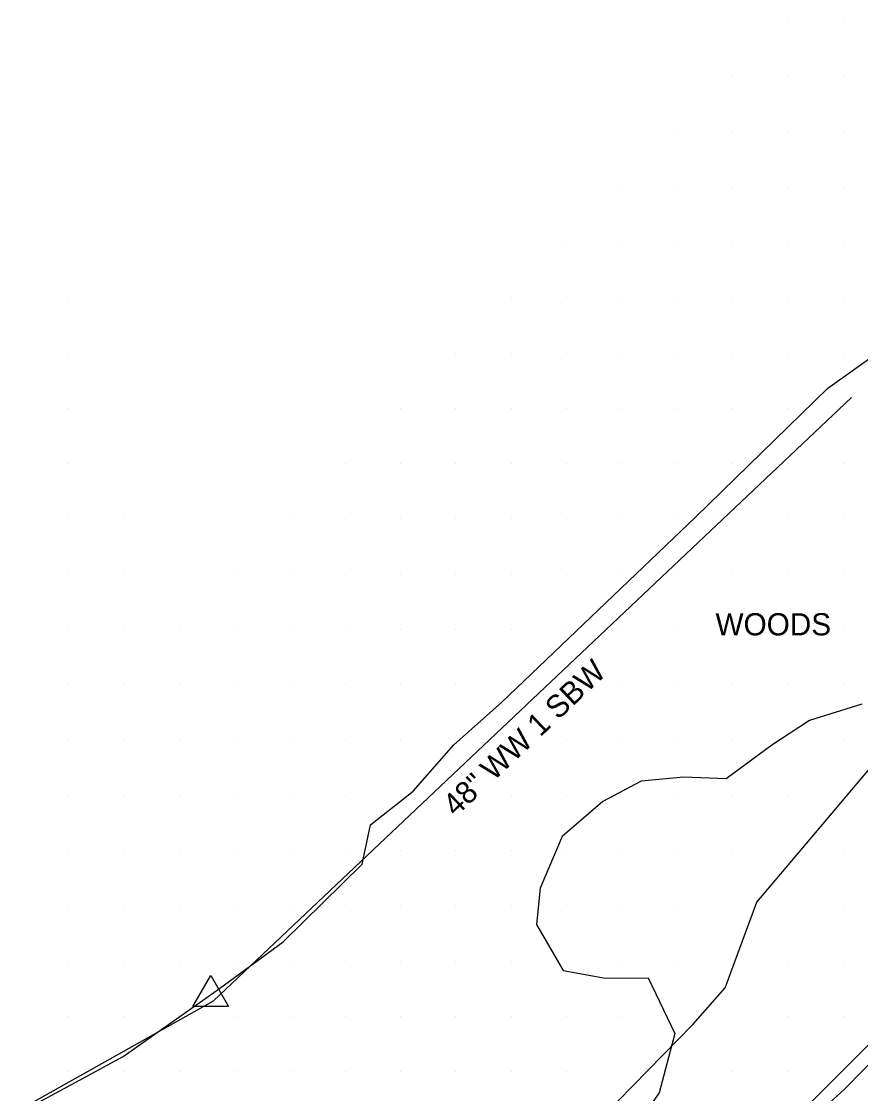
# Model space of a CAD drawing. Extents: x 1548934 to 1561348, y 809680 to 824075.
# Drawn here: x 1551931.4 to 1552083.2, y 811066.1 to 811260 of the extents above; entities that cross this region are included whole.
import ezdxf

# ---------------------------------------------------------------- set-up
doc = ezdxf.new("R2010")
doc.units = 0
for name, color, linetype in [('E_NCDOT_Vertical_Profile_Ground_Line', 7, 'Continuous'), ('Exist DTM QL2 LIDAR Elevation Point', 7, 'Continuous'), ('Exist Other Culture Fence Line Text', 7, 'Continuous'), ('Exist Vegetation Woods Line', 7, 'Continuous'), ('Exist Vegetation Woods Line Text', 7, 'Continuous'), ('P_RDY_Dimension_Text', 7, 'Continuous'), ('PH Exist DTM Breakline', 7, 'Continuous')]:
    doc.layers.add(name, color=color, linetype=linetype)

msp = doc.modelspace()

# ---------------------------------------------------------------- linework, layer by layer
at = {"layer": 'E_NCDOT_Vertical_Profile_Ground_Line'}
msp.add_line((1551965.65, 811083.67), (1551965.65, 811083.67), dxfattribs=at)
msp.add_lwpolyline([(1551962.4, 811081.78), (1551965.65, 811087.42), (1551968.9, 811081.78)], close=True, dxfattribs=at)
at = {"layer": 'Exist DTM QL2 LIDAR Elevation Point'}
for p, q in [((1552070.02, 811260.03), (1552070.02, 811260.03)), ((1552080.03, 811260.03), (1552080.03, 811260.03)), ((1552060.02, 811250.03), (1552060.02, 811250.03)), ((1552070.02, 811250.03), (1552070.02, 811250.03)), ((1552080.03, 811250.03), (1552080.03, 811250.03)), ((1552050.02, 811240.03), (1552050.02, 811240.03)), ((1552060.02, 811240.03), (1552060.02, 811240.03)), ((1552070.02, 811240.03), (1552070.02, 811240.03)), ((1552080.03, 811240.03), (1552080.03, 811240.03)), ((1552040.02, 811230.03), (1552040.02, 811230.03)), ((1552050.02, 811230.03), (1552050.02, 811230.03)), ((1552060.02, 811230.03), (1552060.02, 811230.03)), ((1552070.02, 811230.03), (1552070.02, 811230.03)), ((1552080.03, 811230.03), (1552080.03, 811230.03)), ((1552030.02, 811220.03), (1552030.02, 811220.03)), ((1552040.02, 811220.03), (1552040.02, 811220.03)), ((1552050.02, 811220.03), (1552050.02, 811220.03)), ((1552060.02, 811220.03), (1552060.02, 811220.03)), ((1552070.02, 811220.03), (1552070.02, 811220.03)), ((1552080.03, 811220.03), (1552080.03, 811220.03)), ((1551940.01, 811210.03), (1551940.01, 811210.03)), ((1552020.02, 811210.03), (1552020.02, 811210.03)), ((1552030.02, 811210.03), (1552030.02, 811210.03)), ((1552040.02, 811210.03), (1552040.02, 811210.03)), ((1552050.02, 811210.03), (1552050.02, 811210.03)), ((1552060.02, 811210.03), (1552060.02, 811210.03)), ((1552070.02, 811210.03), (1552070.02, 811210.03)), ((1552080.03, 811210.03), (1552080.03, 811210.03)), ((1551940.01, 811200.03), (1551940.01, 811200.03)), ((1552010.02, 811200.03), (1552010.02, 811200.03)), ((1552020.02, 811200.03), (1552020.02, 811200.03)), ((1552030.02, 811200.03), (1552030.02, 811200.03)), ((1552040.02, 811200.03), (1552040.02, 811200.03)), ((1552050.02, 811200.03), (1552050.02, 811200.03)), ((1552060.02, 811200.03), (1552060.02, 811200.03)), ((1552070.02, 811200.03), (1552070.02, 811200.03)), ((1552080.03, 811200.03), (1552080.03, 811200.03)), ((1551940.01, 811190.03), (1551940.01, 811190.03)), ((1552000.02, 811190.03), (1552000.02, 811190.03)), ((1552010.02, 811190.03), (1552010.02, 811190.03)), ((1552020.02, 811190.03), (1552020.02, 811190.03)), ((1552030.02, 811190.03), (1552030.02, 811190.03)), ((1552040.02, 811190.03), (1552040.02, 811190.03)), ((1552050.02, 811190.03), (1552050.02, 811190.03)), ((1552060.02, 811190.03), (1552060.02, 811190.03)), ((1552070.02, 811190.03), (1552070.02, 811190.03)), ((1552080.03, 811190.03), (1552080.03, 811190.03)), ((1551940.01, 811180.03), (1551940.01, 811180.03)), ((1551990.02, 811180.03), (1551990.02, 811180.03)), ((1552000.02, 811180.03), (1552000.02, 811180.03)), ((1552010.02, 811180.03), (1552010.02, 811180.03)), ((1552020.02, 811180.03), (1552020.02, 811180.03)), ((1552030.02, 811180.03), (1552030.02, 811180.03)), ((1552040.02, 811180.03), (1552040.02, 811180.03)), ((1552050.02, 811180.03), (1552050.02, 811180.03)), ((1552060.02, 811180.03), (1552060.02, 811180.03)), ((1552070.02, 811180.03), (1552070.02, 811180.03)), ((1552080.03, 811180.03), (1552080.03, 811180.03)), ((1551940.01, 811170.02), (1551940.01, 811170.02)), ((1551950.01, 811170.02), (1551950.01, 811170.02)), ((1551980.02, 811170.02), (1551980.02, 811170.02)), ((1551990.02, 811170.02), (1551990.02, 811170.02)), ((1552000.02, 811170.02), (1552000.02, 811170.02)), ((1552010.02, 811170.02), (1552010.02, 811170.02)), ((1552020.02, 811170.02), (1552020.02, 811170.02)), ((1552030.02, 811170.02), (1552030.02, 811170.02)), ((1552040.02, 811170.02), (1552040.02, 811170.02)), ((1552050.02, 811170.02), (1552050.02, 811170.02)), ((1552060.02, 811170.02), (1552060.02, 811170.02)), ((1552070.02, 811170.02), (1552070.02, 811170.02)), ((1552080.03, 811170.02), (1552080.03, 811170.02)), ((1551940.01, 811160.02), (1551940.01, 811160.02)), ((1551950.01, 811160.02), (1551950.01, 811160.02)), ((1551970.02, 811160.02), (1551970.02, 811160.02)), ((1551980.02, 811160.02), (1551980.02, 811160.02)), ((1551990.02, 811160.02), (1551990.02, 811160.02)), ((1552000.02, 811160.02), (1552000.02, 811160.02)), ((1552010.02, 811160.02), (1552010.02, 811160.02)), ((1552020.02, 811160.02), (1552020.02, 811160.02)), ((1552030.02, 811160.02), (1552030.02, 811160.02)), ((1552040.02, 811160.02), (1552040.02, 811160.02)), ((1552050.02, 811160.02), (1552050.02, 811160.02)), ((1552060.02, 811160.02), (1552060.02, 811160.02)), ((1552070.02, 811160.02), (1552070.02, 811160.02)), ((1552080.03, 811160.02), (1552080.03, 811160.02)), ((1551940.01, 811150.02), (1551940.01, 811150.02)), ((1551950.01, 811150.02), (1551950.01, 811150.02)), ((1551960.02, 811150.02), (1551960.02, 811150.02)), ((1551970.02, 811150.02), (1551970.02, 811150.02)), ((1551980.02, 811150.02), (1551980.02, 811150.02)), ((1551990.02, 811150.02), (1551990.02, 811150.02)), ((1552000.02, 811150.02), (1552000.02, 811150.02)), ((1552010.02, 811150.02), (1552010.02, 811150.02)), ((1552020.02, 811150.02), (1552020.02, 811150.02)), ((1552030.02, 811150.02), (1552030.02, 811150.02)), ((1552040.02, 811150.02), (1552040.02, 811150.02)), ((1552050.02, 811150.02), (1552050.02, 811150.02)), ((1552060.02, 811150.02), (1552060.02, 811150.02)), ((1552070.02, 811150.02), (1552070.02, 811150.02)), ((1552080.03, 811150.02), (1552080.03, 811150.02)), ((1551940.01, 811140.02), (1551940.01, 811140.02)), ((1551950.01, 811140.02), (1551950.01, 811140.02)), ((1551960.02, 811140.02), (1551960.02, 811140.02)), ((1551970.02, 811140.02), (1551970.02, 811140.02)), ((1551980.02, 811140.02), (1551980.02, 811140.02)), ((1551990.02, 811140.02), (1551990.02, 811140.02)), ((1552000.02, 811140.02), (1552000.02, 811140.02)), ((1552010.02, 811140.02), (1552010.02, 811140.02)), ((1552020.02, 811140.02), (1552020.02, 811140.02)), ((1552030.02, 811140.02), (1552030.02, 811140.02)), ((1552040.02, 811140.02), (1552040.02, 811140.02)), ((1552050.02, 811140.02), (1552050.02, 811140.02)), ((1552060.02, 811140.02), (1552060.02, 811140.02)), ((1552070.02, 811140.02), (1552070.02, 811140.02)), ((1552080.03, 811140.02), (1552080.03, 811140.02)), ((1551940.01, 811130.02), (1551940.01, 811130.02)), ((1551950.01, 811130.02), (1551950.01, 811130.02)), ((1551960.02, 811130.02), (1551960.02, 811130.02)), ((1551970.02, 811130.02), (1551970.02, 811130.02)), ((1551980.02, 811130.02), (1551980.02, 811130.02)), ((1551990.02, 811130.02), (1551990.02, 811130.02)), ((1552000.02, 811130.02), (1552000.02, 811130.02)), ((1552010.02, 811130.02), (1552010.02, 811130.02)), ((1552020.02, 811130.02), (1552020.02, 811130.02)), ((1552030.02, 811130.02), (1552030.02, 811130.02)), ((1552040.02, 811130.02), (1552040.02, 811130.02)), ((1552050.02, 811130.02), (1552050.02, 811130.02)), ((1552060.02, 811130.02), (1552060.02, 811130.02)), ((1552070.02, 811130.02), (1552070.02, 811130.02)), ((1552080.03, 811130.02), (1552080.03, 811130.02)), ((1551940.01, 811120.02), (1551940.01, 811120.02)), ((1551950.01, 811120.02), (1551950.01, 811120.02)), ((1551960.02, 811120.02), (1551960.02, 811120.02)), ((1551970.02, 811120.02), (1551970.02, 811120.02)), ((1551980.02, 811120.02), (1551980.02, 811120.02)), ((1551990.02, 811120.02), (1551990.02, 811120.02)), ((1552000.02, 811120.02), (1552000.02, 811120.02)), ((1552010.02, 811120.02), (1552010.02, 811120.02)), ((1552020.02, 811120.02), (1552020.02, 811120.02)), ((1552030.02, 811120.02), (1552030.02, 811120.02)), ((1552040.02, 811120.02), (1552040.02, 811120.02)), ((1552050.02, 811120.02), (1552050.02, 811120.02)), ((1552060.02, 811120.02), (1552060.02, 811120.02)), ((1552070.02, 811120.02), (1552070.02, 811120.02)), ((1551940.01, 811110.02), (1551940.01, 811110.02)), ((1551950.01, 811110.02), (1551950.01, 811110.02)), ((1551960.02, 811110.02), (1551960.02, 811110.02)), ((1551970.02, 811110.02), (1551970.02, 811110.02)), ((1551980.02, 811110.02), (1551980.02, 811110.02)), ((1551990.02, 811110.02), (1551990.02, 811110.02)), ((1552000.02, 811110.02), (1552000.02, 811110.02)), ((1552010.02, 811110.02), (1552010.02, 811110.02)), ((1552020.02, 811110.02), (1552020.02, 811110.02)), ((1552030.02, 811110.02), (1552030.02, 811110.02)), ((1552040.02, 811110.02), (1552040.02, 811110.02)), ((1552050.02, 811110.02), (1552050.02, 811110.02)), ((1552060.02, 811110.02), (1552060.02, 811110.02)), ((1552080.03, 811110.02), (1552080.03, 811110.02)), ((1551940.01, 811100.02), (1551940.01, 811100.02)), ((1551950.01, 811100.02), (1551950.01, 811100.02)), ((1551960.02, 811100.02), (1551960.02, 811100.02)), ((1551970.02, 811100.02), (1551970.02, 811100.02)), ((1551980.02, 811100.02), (1551980.02, 811100.02)), ((1551990.02, 811100.02), (1551990.02, 811100.02)), ((1552000.02, 811100.02), (1552000.02, 811100.02)), ((1552010.02, 811100.02), (1552010.02, 811100.02)), ((1552020.02, 811100.02), (1552020.02, 811100.02)), ((1552030.02, 811100.02), (1552030.02, 811100.02)), ((1552040.02, 811100.02), (1552040.02, 811100.02)), ((1552050.02, 811100.02), (1552050.02, 811100.02)), ((1552080.03, 811100.02), (1552080.03, 811100.02)), ((1551940.01, 811090.02), (1551940.01, 811090.02)), ((1551950.01, 811090.02), (1551950.01, 811090.02)), ((1551960.02, 811090.02), (1551960.02, 811090.02)), ((1551970.02, 811090.02), (1551970.02, 811090.02)), ((1551980.02, 811090.02), (1551980.02, 811090.02)), ((1551990.02, 811090.02), (1551990.02, 811090.02)), ((1552000.02, 811090.02), (1552000.02, 811090.02)), ((1552010.02, 811090.02), (1552010.02, 811090.02)), ((1552020.02, 811090.02), (1552020.02, 811090.02)), ((1552030.02, 811090.02), (1552030.02, 811090.02)), ((1552040.02, 811090.02), (1552040.02, 811090.02)), ((1552050.02, 811090.02), (1552050.02, 811090.02)), ((1552070.02, 811090.02), (1552070.02, 811090.02)), ((1552080.03, 811090.02), (1552080.03, 811090.02)), ((1551940.01, 811080.02), (1551940.01, 811080.02)), ((1551950.01, 811080.02), (1551950.01, 811080.02)), ((1551960.02, 811080.02), (1551960.02, 811080.02)), ((1551970.02, 811080.02), (1551970.02, 811080.02)), ((1551980.02, 811080.02), (1551980.02, 811080.02)), ((1551990.02, 811080.02), (1551990.02, 811080.02)), ((1552000.02, 811080.02), (1552000.02, 811080.02)), ((1552010.02, 811080.02), (1552010.02, 811080.02)), ((1552020.02, 811080.02), (1552020.02, 811080.02)), ((1552030.02, 811080.02), (1552030.02, 811080.02)), ((1552040.02, 811080.02), (1552040.02, 811080.02)), ((1552070.02, 811080.02), (1552070.02, 811080.02)), ((1552080.03, 811080.02), (1552080.03, 811080.02)), ((1551940.01, 811070.02), (1551940.01, 811070.02)), ((1551950.01, 811070.02), (1551950.01, 811070.02)), ((1551960.02, 811070.02), (1551960.02, 811070.02)), ((1551970.02, 811070.02), (1551970.02, 811070.02)), ((1551980.02, 811070.02), (1551980.02, 811070.02)), ((1551990.02, 811070.02), (1551990.02, 811070.02)), ((1552000.02, 811070.02), (1552000.02, 811070.02)), ((1552010.02, 811070.02), (1552010.02, 811070.02)), ((1552020.02, 811070.02), (1552020.02, 811070.02)), ((1552030.02, 811070.02), (1552030.02, 811070.02)), ((1552060.02, 811070.02), (1552060.02, 811070.02)), ((1552070.02, 811070.02), (1552070.02, 811070.02))]:
    msp.add_line(p, q, dxfattribs=at)
at = {"layer": 'Exist Vegetation Woods Line'}
for points in [[(1551949.83, 811072.75), (1551967.23, 811085.09), (1551978.74, 811093.51), (1551993.04, 811107.54), (1551994.56, 811114.68), (1552002.25, 811120.75), (1552009.65, 811129.12), (1552018.27, 811136.78), (1552053.32, 811170.34), (1552077.3, 811193.66), (1552100.15, 811209.98)], [(1552083.42, 811136.51), (1552073.94, 811133.55), (1552067.17, 811129.1), (1552058.88, 811122.99), (1552051.23, 811123.32), (1552043.49, 811122.55), (1552036.6, 811118.92), (1552029.21, 811112.58), (1552025.25, 811103.22), (1552024.57, 811096.66), (1552029.41, 811088.34), (1552037.09, 811086.92), (1552044.76, 811086.98), (1552049.62, 811076.93), (1552046.76, 811066.19), (1552040.8, 811057.7)], [(1551977.93, 810998.3), (1551970.88, 810994.36), (1551960.15, 810989.16), (1551950.01, 810984.47), (1551942.26, 810982.58), (1551935.79, 810981.88), (1551927.04, 810985.6), (1551917.17, 810997.94), (1551912.39, 811001.64), (1551905.64, 811006.2), (1551898.94, 811010.16), (1551894.03, 811013.82), (1551889.51, 811019.9), (1551884.86, 811024.1), (1551880.67, 811028.77), (1551884.61, 811037.75), (1551893.7, 811042.39), (1551949.83, 811072.75)]]:
    msp.add_lwpolyline(points, dxfattribs=at)
at = {"layer": 'P_RDY_Dimension_Text'}
msp.add_line((1551966.16, 811082.82), (1552081.55, 811192.02), dxfattribs=at)
msp.add_lwpolyline([(1551792.63, 810879.89), (1551798.87, 810886.61), (1551791.81, 810954.68), (1551790.16, 810983.57), (1551796.35, 810987.52), (1551966.16, 811082.82)], dxfattribs=at)
at = {"layer": 'PH Exist DTM Breakline'}
for points in [[(1551964.87, 811011.81), (1551975.75, 811017.5), (1551993.21, 811028.9), (1552019.58, 811044.66), (1552036.56, 811061.92), (1552052.87, 811078.54), (1552058.72, 811085.17), (1552064.45, 811100.69), (1552073.41, 811111.32), (1552085.56, 811125.66), (1552095.43, 811130.85), (1552112.53, 811138.38), (1552127.13, 811144.62), (1552136.95, 811150.64)], [(1551976.06, 810969.12), (1551985.65, 810979.8), (1551992.95, 810987.24), (1551997.82, 810992.11), (1552006.04, 810999.75), (1552010.84, 811004.55), (1552015.46, 811008.38), (1552024.58, 811015.75), (1552030.32, 811021.53), (1552038.79, 811029.81), (1552047.22, 811037.78), (1552058.63, 811048.94), (1552067.82, 811057.98), (1552078.4, 811068.68), (1552086.91, 811077.17), (1552097.9, 811087.2), (1552108.72, 811097.64), (1552127.22, 811115.39), (1552138.18, 811125.76), (1552150.17, 811138.94)], [(1551976.37, 810967.37), (1551990.02, 810981.53), (1552001.33, 810991.79), (1552010.23, 811000.09), (1552024.35, 811013.28), (1552036.33, 811024.4), (1552051.57, 811038.4), (1552060.65, 811048.24), (1552069.18, 811056.77), (1552080.24, 811066.77), (1552090.88, 811077.64), (1552102.68, 811090.03), (1552112.72, 811099.39), (1552122.5, 811106.78), (1552140.47, 811123.19), (1552153.6, 811136.59)]]:
    msp.add_lwpolyline(points, dxfattribs=at)

# ---------------------------------------------------------------- texts
at = {"layer": 'Exist Other Culture Fence Line Text'}
msp.add_text('48" WW 1 SBW', height=4.02, rotation=43.4252, dxfattribs=at).set_placement((1552009.98, 811116.02))
at = {"layer": 'Exist Vegetation Woods Line Text'}
msp.add_text('WOODS', height=4.02, dxfattribs=at).set_placement((1552056.96, 811148.95))

doc.saveas('drawing.dxf')
